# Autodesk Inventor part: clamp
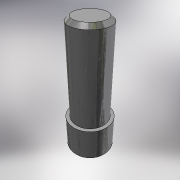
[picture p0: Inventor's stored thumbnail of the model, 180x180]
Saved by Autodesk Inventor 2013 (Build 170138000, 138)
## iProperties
Shininess: 64.0
Length Units: 11269
Angle Units: 11279
Time Units: 11290
Mass Units: 11283
Length Display Precision: 3
Angle Display Precision: 2
Compacted: True
Part Number: clamp
Document SubType Name: Modeling
Created: 2005-02
Material: Stainless Steel, 440C
Designer: =<Author>
Manufacturer: Standard
Standards Organization: Custom
Description: Clamp
Density: 7.75 g/cm^3
Mass: 23.7305 g
Surface Area: 13.4549 cm^2
Volume: 3.06201 cm^3
Density: 0.0
Volumn: 0.0
Area: 0.0
PropertySet Name: Model Information
Control State: 0
Master: False
Checked Out: False
Checked Out Date: 2008-10-15
Last Check In Date: 2008-10-15
Author: PVitaliy
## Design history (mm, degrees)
sketch "Эскиз1"
  geometry: C1 r 6 at (0, 0)
  constraints: 1 centre point, 1 other
  dimensions: "d0" = 12 diameter of C1
extrude "Выдавливание1" new body sketch "Эскиз1" distance "d1" = 10; taper "d2" = 0 deg
sketch "Эскиз2"
  geometry: C1 r 6 at (0, 0) reference; C2 r 5 at (0, 0)
  constraints: 1 centre point, 1 coincident
  dimensions: "d3" = 10 diameter of C2
extrude "Выдавливание2" join sketch "Эскиз2" distance "d4" = 25; taper "d5" = 0 deg
chamfer "Фаска1" distance "d6" = 1; stored, may be unused: second distance "d7" = 2, angle "d8" = 45 deg
body "Solid1"
